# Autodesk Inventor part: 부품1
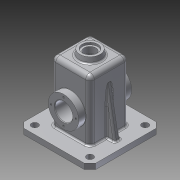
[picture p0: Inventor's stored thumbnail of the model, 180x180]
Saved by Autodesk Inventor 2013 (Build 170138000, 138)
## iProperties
Created: 2016-02
Part Number: 부품1
Material: 알루미늄 6061
Document SubType Name: Modeling
Designer: dgall
Mass: 932.813 g
Surface Area: 1043.48 cm^2
Volume: 344.212 cm^3
Density: 2.71 g/cm^3
Author: dgall
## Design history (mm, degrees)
sketch "스케치1"
  geometry: L1 (-35, -35)-(35, -35); L2 (35, -35)-(35, 35); L3 (35, 35)-(-35, 35); L4 (-35, 35)-(-35, -35); L5 (-35, -35)-(35, 35); L6 (35, -35)-(-35, 35); 1 further point
  constraints: 12 end point, 2 midpoint, 2 parallel, 1 horizontal, 1 perpendicular
  dimensions: "d0" = 70 distance of L2.end L3.end; "d2" = 70 distance of L1.end L2.end
extrude "돌출1" new body sketch "스케치1" distance "d3" = 110; taper "d4" = 0 deg
fillet "모깎기1" dims "d5" = 8
feature "쉘1" dims "d6" = 5
sketch "스케치2"
  geometry: L1 (-27, 35)-(27, 35) reference; L2 (-35, -27)-(-35, 27) reference; L3 (27, -35)-(-27, -35) reference; L4 (35, 27)-(35, -27) reference; L5 (30, 27)-(30, -27); L6 (27, -30)-(-27, -30); L7 (-30, -27)-(-30, 27); L8 (-27, 30)-(27, 30); A1 r 8 centre (27, 27) between (35, 27) and (27, 35) reference; A2 r 8 centre (-27, 27) between (-27, 35) and (-35, 27) reference; A3 r 8 centre (-27, -27) between (-35, -27) and (-27, -35) reference; A4 r 8 centre (27, -27) between (27, -35) and (35, -27) reference; A5 r 3 centre (27, 27) between (30, 27) and (27, 30); A6 r 3 centre (27, -27) between (27, -30) and (30, -27); A7 r 3 centre (-27, -27) between (-30, -27) and (-27, -30); A8 r 3 centre (-27, 27) between (-27, 30) and (-30, 27); 1 further point
  constraints: 8 end point, 8 point on circle, 4 centre point, 7 other
  dimensions: "d7" = 5 distance between parallel lines of L1 L8
extrude "돌출2" cut sketch "스케치2" distance "d8" = 5; taper "d9" = 0 deg
sketch "스케치3"
  geometry: L1 (-27, 30)-(27, 30) reference; L2 (30, 27)-(30, -27) reference; L3 (27, -30)-(-27, -30) reference; L4 (-30, -27)-(-30, 27) reference; L5 (-65, -65)-(65, -65); L6 (65, -65)-(65, 65); L7 (65, 65)-(-65, 65); L8 (-65, 65)-(-65, -65); L9 (-65, -65)-(65, 65); L10 (65, -65)-(-65, 65); A1 r 3 centre (27, 27) between (30, 27) and (27, 30) reference; A2 r 3 centre (27, -27) between (27, -30) and (30, -27) reference; A3 r 3 centre (-27, -27) between (-30, -27) and (-27, -30) reference; A4 r 3 centre (-27, 27) between (-27, 30) and (-30, 27) reference; 1 further point
  constraints: 12 end point, 2 midpoint, 2 parallel, 1 horizontal, 1 perpendicular
  dimensions: "d10" = 130 distance of L6.end L7.end; "d12" = 130 distance of L5.end L6.end
extrude "돌출3" join sketch "스케치3" distance "d13" = 10; taper "d14" = 0 deg
chamfer "모따기1" distance "d15" = 10; stored, may be unused: second distance "d16" = 2, angle "d17" = 45 deg
sketch "스케치5"
  geometry: C1 r 20 at (0, 0); 1 further point
  constraints: 1 centre point, 1 coincident
  dimensions: "d20" = 40 diameter of C1
extrude "돌출4" join sketch "스케치5" distance "d22" = 10; taper "d23" = -10 deg
sketch "스케치6"
  geometry: C1 r 18.237 at (0, 0) reference; C2 r 14 at (0, 0)
  constraints: 1 centre point, 1 coincident
  dimensions: "d24" = 28 diameter of C2
extrude "돌출5" cut sketch "스케치6" distance "d26" = 4; taper "d27" = 0 deg
sketch "스케치7"
  geometry: C1 r 14 at (0, 0) reference; C2 r 10.5 at (0, 0)
  constraints: 1 centre point, 1 coincident
  dimensions: "d28" = 21 diameter of C2
extrude "돌출6" cut sketch "스케치7" stored distance "d30" = 5; taper "d31" = 0 deg
fillet "모깎기2" dims "d32" = 3
node "작업 평면3"
sketch "스케치8"
  geometry: L1 (19.563, 112.479)-(18.237, 120) reference; L2 (-27, 110)-(27, 110) reference; L3 (35, 102)-(35, 0) reference; L4 (30, 102)-(30, -10) reference; L5 (-30, -10)-(-30, 102) reference; L6 (-35, 0)-(-35, 102) reference; L7 (-55, 0)-(55, 0) reference; L8 (55, 0)-(65, 0) reference; L9 (-65, 0)-(-55, 0) reference; L10 (-50, 0)-(-35, 85.069); L11 (50, 0)-(35, 85.069); L12 (65, 0)-(65, -10) reference; L13 (-65, -10)-(-65, 0) reference; 1 further point
  constraints: 4 end point, 4 point on line
  dimensions: "d34" = 10 deg angle of L12 L11; "d35" = 10 deg angle of L13 L10; "d36" = 15 distance from line of L12 L11.start; "d37" = 15 distance from line of L13 L10.start
extrude "돌출7" join sketch "스케치8" stored distance "d38" = 10; taper "d39" = 0 deg
fillet "모깎기3" dims "d40" = 3
fillet "모깎기4" dims "d41" = 3
fillet "모깎기5" dims "d42" = 3
node "작업 평면5"
sketch "스케치9"
  geometry: L1 (-55, -10)-(55, -10) reference; L2 (-50.917, 45)-(75.11, 45); L3 (35, 102)-(35, 3) reference; L4 (30, 102)-(30, -10) reference; L5 (-30, -10)-(-30, 102) reference; L6 (-35, 3)-(-35, 102) reference; L7 (35, 72.5)-(48, 72.5); L8 (48, 72.5)-(48, 45); L9 (30, 72.5)-(23, 65.5); L10 (23, 65.5)-(23, 45); L11 (23, 61)-(48, 61); L12 (35, 72.5)-(35, 61); L13 (30, 72.5)-(30, 61); 1 further point
  constraints: 16 end point, 10 point on line, 4 perpendicular
  dimensions: "d47" = 55 distance between parallel lines of L1 L2; "d48" = 55 diameter of L7 L2; "d49" = 55 diameter of L9.start L2; "d50" = 135 deg angle of L4 L9; "d51" = 7 distance between parallel lines of L4 L10; "d52" = 13 distance between parallel lines of L3 L8; "d53" = 126.02672 distance of L2.start L2.end; "d54" = 50.91704 horizontal distance of point (0, 0) L2.start; "d55" = 32 diameter of L11 L2
revolve "회전1" sketch "스케치9" stored, may be unused: angle "d56" = 90 deg
sketch "스케치10"
  geometry: C1 r 16 at (0, 0) reference; C2 r 16 at (0, 0); 1 further point
  constraints: 1 centre point, 1 coincident
  dimensions: "d57" = 32 diameter of C2
extrude "돌출8" cut sketch "스케치10" stored distance "d59" = 10; taper "d60" = 0 deg
sketch "스케치12"
  geometry: C1 r 16 at (0, 0) reference; C2 r 16 at (0, 0); 1 further point
  constraints: 1 centre point, 1 coincident
  dimensions: "d61" = 32 diameter of C2
extrude "돌출9" cut sketch "스케치12" stored distance "d63" = 10; taper "d64" = 0 deg
sketch "스케치13"
  geometry: L1 (0, -22.5)-(0, 22.5); L2 (22.5, 0)-(-22.5, 0); C1 r 27.5 at (0, 0) reference; A1 r 22.5 centre (0, 0) between (0, -22.5) and (0, 22.5); 3 further points
  constraints: 4 end point, 4 midpoint, 4 point on circle, 1 centre point, 1 coincident, 1 perpendicular, 1 vertical
  dimensions: "d65" = 45 diameter of A1
hole "구멍1" sketch "스케치13" at (0, 22.5), (-22.5, 0), (0, -22.5), (22.5, 0) diameter "d67" = 3.242; stored, may be unused: countersink angle "d71" = 90 deg, drill point angle "d73" = 118 deg; dims "d68" = 8, "d69" = 4, "d70" = 2, "d72" = 10
fillet "모깎기6" dims "d74" = 0.5
fillet "모깎기7" dims "d75" = 0.5
fillet "모깎기8" dims "d76" = 0.5
sketch "스케치15"
  geometry: L1 (65, 55)-(65, -55) reference; L2 (-55, 65)-(55, 65) reference; L3 (-65, -55)-(-65, 55) reference; C1 r 6 at (-50, 50); C2 r 6 at (50, 50); C3 r 6 at (-50, -50); C4 r 6 at (50, -50); 1 further point
  constraints: 4 centre point
  dimensions: "d77" = 100 distance of C2.centre C1.centre; "d79" = 100 distance of C1.centre C3.centre; "d80" = 100 distance of C4.centre C2.centre; "d81" = 100 distance of C3.centre C4.centre; "d82" = 15 distance from line of L2 C2.centre; "d83" = 15 distance from line of L1 C2.centre; "d84" = 12 diameter of C1; "d85" = 12 diameter of C2; "d86" = 12 diameter of C4; "d87" = 12 diameter of C3; "d88" = 15 distance from line of L2 C1.centre; "d89" = 15 distance from line of L3 C3.centre
extrude "돌출10" cut sketch "스케치15" stored distance "d90" = 10; taper "d91" = 0 deg
sketch "스케치16"
  geometry: L1 (47.739, 8.998)-(6.261, 8.998); L2 (6.261, 8.998)-(6.261, 15.002); L3 (6.261, 15.002)-(47.739, 15.002); L4 (47.739, 15.002)-(47.739, 8.998); L5 (47.739, 12)-(6.261, 12); L6 (27, 8.998)-(27, 15.002); L7 (45.237, -18)-(8.763, -18) reference; L8 (-8, 99)-(-8, 0) reference; 1 further point
  constraints: 4 end point, 4 midpoint, 2 other
  dimensions: "d93" = 35 distance between parallel lines of L8 L6; "d94" = 30 distance between parallel lines of L7 L5
extrude "돌출11" join sketch "스케치16" distance "d95" = 0.5; taper "d96" = 0 deg
chamfer "모따기2" distance "d97" = 1; stored, may be unused: second distance "d98" = 2, angle "d99" = 45 deg
node "솔리드1"
mirror "대칭1"
mirror "대칭2"
other parameters: "d33" = 0, "d44" = 0
